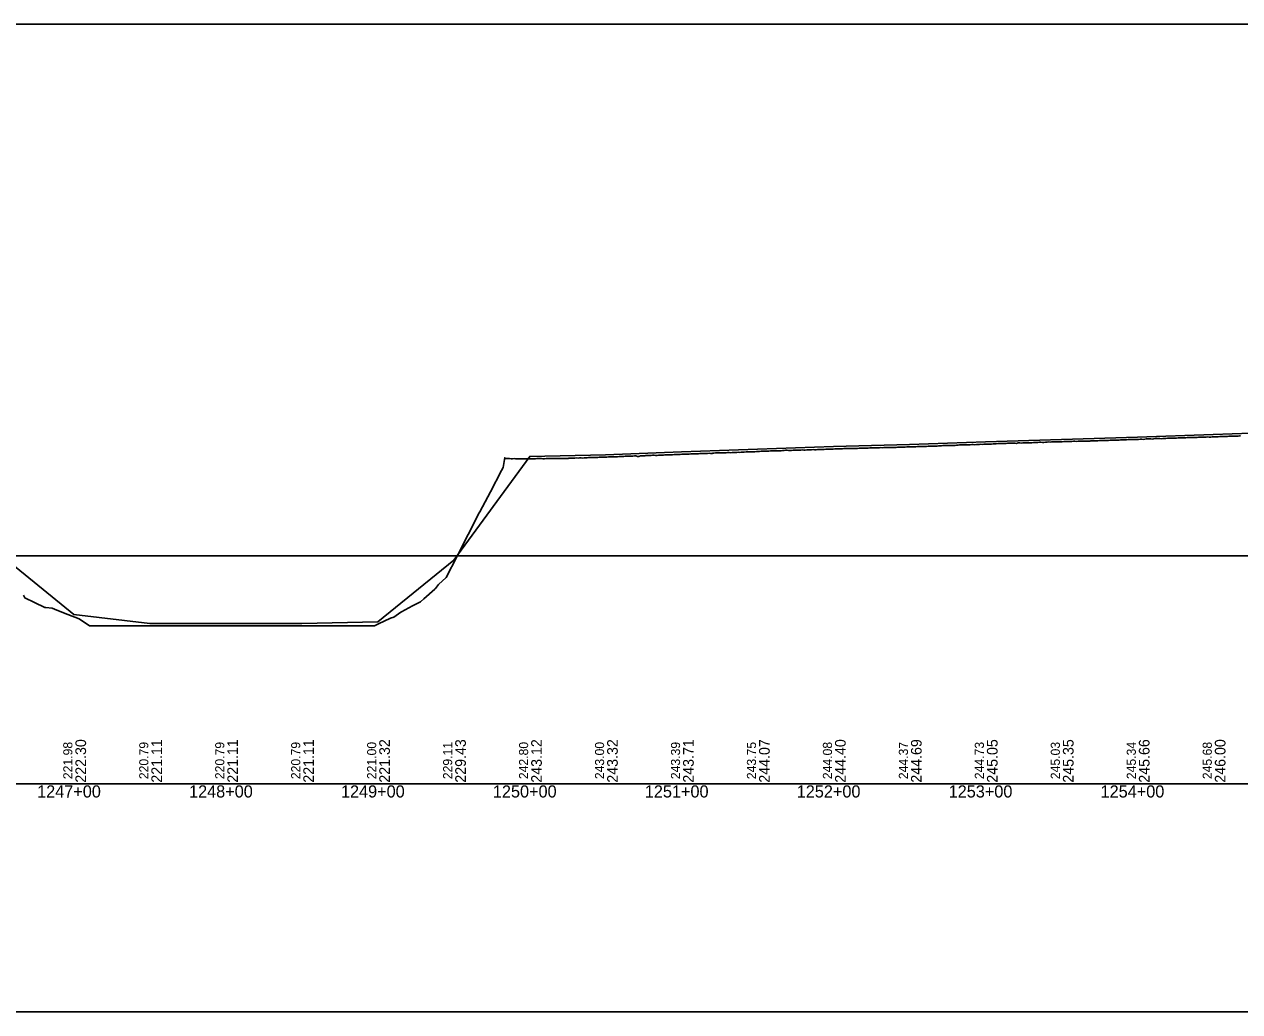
# Model space of a CAD drawing. Extents: x -3627 to 47473, y 2850 to 4350.
# Drawn here: x 12045 to 12845, y 2850 to 3500 of the extents above; entities that cross this region are included whole.
import ezdxf

# ---------------------------------------------------------------- set-up
doc = ezdxf.new("R2010")
doc.units = 0
for name, color, linetype in [('RD_DDB_Profile_EX', 7, 'Continuous'), ('RD_DDB_Profile_PR', 7, 'Continuous'), ('RD_DDB_StaTX', 7, 'Continuous'), ('RD_DDB_StripGrade', 7, 'Continuous'), ('RD_GPK_Profile_Cell', 7, 'Continuous'), ('RD_SHT_ShtClip', 7, 'Continuous')]:
    doc.layers.add(name, color=color, linetype=linetype)

msp = doc.modelspace()

# ---------------------------------------------------------------- linework, layer by layer
at = {"layer": 'RD_DDB_Profile_EX'}
for points in [[(12595.18229, 3220.917655), (12596.179708, 3220.93725), (12597.183113, 3220.978635), (12598.180536, 3220.98066), (12599.183936, 3221.051895), (12600.243634, 3221.062645), (12601.184864, 3221.115985), (12602.182411, 3221.15857), (12603.178695, 3221.15884), (12604.182196, 3221.200265), (12605.260439, 3221.213145), (12606.264547, 3221.21172), (12607.560844, 3221.29361), (12608.534436, 3221.33665), (12609.532153, 3221.269425), (12610.532749, 3221.308945), (12611.53669, 3221.37191), (12612.53861, 3221.373765), (12613.53501, 3221.41641), (12614.536917, 3221.511955), (12614.878053, 3221.49483), (12615.533435, 3221.432655), (12616.535513, 3221.43412), (12617.532093, 3221.46931), (12618.532893, 3221.442675), (12619.530743, 3221.57771), (12620.531541, 3221.586655), (12621.529385, 3221.571665), (12622.530244, 3221.572965), (12623.528267, 3221.607995), (12624.529246, 3221.69517), (12625.526012, 3221.744495), (12626.535868, 3221.80815), (12627.532631, 3221.85754), (12628.530665, 3221.856675), (12629.531642, 3221.81503), (12630.530563, 3221.942775), (12631.531715, 3221.929625), (12632.528673, 3221.97138), (12633.531093, 3222.04359), (12634.528055, 3222.042575), (12635.530473, 3222.078955), (12636.527439, 3222.12817), (12636.829683, 3222.128495), (12637.52999, 3222.12859), (12638.527152, 3222.12754), (12639.528483, 3222.220925), (12640.526929, 3222.29784), (12641.535868, 3222.24693), (12642.584716, 3222.260745), (12643.586412, 3222.31895), (12644.583336, 3222.36824), (12645.585336, 3222.368835), (12646.436473, 3222.495595), (12647.353757, 3222.53258), (12648.34842, 3222.60685), (12649.351012, 3222.628885), (12650.346788, 3222.67372), (12651.464102, 3222.666705), (12652.344042, 3222.69877), (12653.351913, 3222.771535), (12654.353461, 3222.81537), (12655.349212, 3222.817265), (12656.351829, 3222.73086), (12657.346512, 3222.826265), (12658.349128, 3222.863615), (12658.781312, 3222.86459), (12659.344062, 3222.85229), (12660.345687, 3223.07057), (12661.34833, 3223.12188), (12662.344052, 3223.11716), (12663.345693, 3223.161135), (12664.346741, 3223.158905), (12665.349383, 3223.165095), (12666.352033, 3223.239595), (12667.346775, 3223.178855), (12668.349443, 3223.278595), (12669.345137, 3223.297925), (12670.346854, 3223.24788), (12671.342538, 3223.34306), (12672.345208, 3223.35473), (12673.415731, 3223.37456), (12674.342636, 3223.520085), (12675.350711, 3223.48328), (12676.345477, 3223.50761), (12677.348174, 3223.62813), (12678.343853, 3223.60221), (12679.345637, 3223.690355), (12680.348334, 3223.68401), (12680.732941, 3223.684485), (12681.344031, 3223.68484), (12682.345844, 3223.78416), (12683.404348, 3223.78509), (12684.406534, 3223.83441), (12685.410311, 3223.939595), (12686.409477, 3223.96429), (12687.411675, 3224.007785), (12688.406596, 3223.99855), (12689.408993, 3224.047665), (12689.868477, 3224.09275), (12690.864861, 3224.093365)], [(12690.864861, 3224.093365), (12691.866756, 3224.16412), (12692.867594, 3224.223), (12693.863062, 3224.20753), (12694.864976, 3224.23389), (12695.367361, 3224.23536), (12695.865839, 3224.220465), (12696.868669, 3224.157735), (12697.864174, 3224.15199), (12698.865042, 3224.42761), (12699.867019, 3224.420735), (12700.862515, 3224.371365), (12701.863594, 3224.473825), (12702.866231, 3224.477795), (12703.861119, 3224.45435), (12704.869179, 3224.47844), (12705.864705, 3224.51287), (12706.859594, 3224.46813), (12707.868499, 3224.584375), (12708.863388, 3224.68962), (12710.00178, 3224.7055), (12710.867014, 3224.69833), (12711.861945, 3224.74788), (12712.870894, 3224.8242), (12713.865824, 3224.873825), (12714.86139, 3224.755295), (12715.868864, 3224.73955), (12716.864429, 3224.918405), (12717.31899, 3224.96256), (12717.867154, 3225.026845), (12718.868374, 3225.06753), (12719.863989, 3225.022375), (12720.866088, 3225.04147), (12721.867104, 3225.03765), (12722.862724, 3225.03188), (12723.865686, 3225.073805), (12724.866703, 3225.186305), (12725.894757, 3225.1893), (12726.890599, 3225.210795), (12727.891368, 3225.117825), (12728.894669, 3225.27641), (12729.890522, 3225.27569), (12730.261901, 3225.27701), (12731.364928, 3225.34085), (12731.953409, 3225.40041), (12732.365101, 3225.425735), (12733.365446, 3225.421435), (12734.259436, 3225.33305), (12735.357693, 3225.475515), (12736.25508, 3225.52136), (12737.361785, 3225.41973), (12738.262719, 3225.510875), (12739.353989, 3225.54352), (12740.354619, 3225.544205), (12741.355249, 3225.56623), (12742.260835, 3225.612275), (12743.347549, 3225.683875), (12744.348175, 3225.680045), (12745.257042, 3225.680785), (12746.264132, 3225.684135), (12746.587829, 3225.71773), (12747.345551, 3225.782475), (12748.346474, 3225.87858), (12749.347028, 3225.85043), (12750.261589, 3225.850775), (12751.340221, 3225.890415), (12752.341142, 3225.94504), (12753.342063, 3226.024545), (12753.905039, 3226.02482), (12754.259571, 3226.024835), (12755.338437, 3225.95421), (12756.339661, 3225.99626), (12757.340885, 3226.042305), (12758.342109, 3226.070255), (12759.334614, 3226.214125), (12760.335506, 3226.260055), (12761.258446, 3226.21398), (12762.329549, 3226.26164), (12763.253864, 3226.307485), (12764.336523, 3226.328375), (12765.262283, 3226.32813), (12766.33049, 3226.418115), (12767.33202, 3226.414065), (12768.539458, 3226.460045), (12769.175199, 3226.45608), (12770.168504, 3226.507445), (12771.17459, 3226.57013), (12772.167529, 3226.624755), (12773.168578, 3226.64181), (12774.170276, 3226.662735), (12775.167957, 3226.713035), (12776.169731, 3226.71568), (12777.163226, 3226.68401), (12778.165172, 3226.76907), (12779.17151, 3226.91346), (12780.164991, 3226.91447), (12781.166942, 3226.723725), (12782.173279, 3226.842035), (12783.173878, 3227.032835), (12784.167997, 3227.081365), (12785.161714, 3227.131865)], [(12785.161714, 3227.131865), (12786.1683, 3227.13607), (12787.170487, 3226.94517), (12788.164201, 3227.17857), (12789.166399, 3227.237655), (12790.164483, 3227.243325), (12790.491087, 3227.25927), (12791.166854, 3227.28867), (12792.169305, 3227.240745), (12793.16327, 3227.158285), (12794.169761, 3227.348135), (12795.172211, 3227.393415), (12796.165543, 3227.39367), (12797.172358, 3227.4871), (12798.166415, 3227.48717), (12799.169122, 3227.489035), (12800.171829, 3227.583735), (12801.170409, 3227.58551), (12802.173124, 3227.583785), (12803.167376, 3227.587345), (12804.170109, 3227.72815), (12805.176804, 3227.735715), (12806.171327, 3227.78912), (12807.159993, 3227.77991), (12808.162271, 3227.73218), (12809.161123, 3227.829945), (12810.163394, 3227.92425), (12810.607658, 3227.923805), (12811.607457, 3227.97565), (12812.607261, 3227.977445), (12813.608652, 3227.97141), (12814.608492, 3227.93842), (12815.608331, 3228.035945), (12816.601985, 3228.085405), (12817.609091, 3228.131475), (12818.608943, 3228.179205), (12819.759926, 3228.18809), (12820.603512, 3228.23359), (12821.610676, 3228.28317), (12822.610557, 3228.284335), (12823.604704, 3228.32994), (12824.604578, 3228.28841), (12825.61175, 3228.288015), (12826.605897, 3228.38735), (12827.077136, 3228.387865), (12827.605794, 3228.39193), (12828.60571, 3228.431955), (12829.607192, 3228.47554), (12830.60711, 3228.537525), (12831.607029, 3228.584715), (12832.601218, 3228.630055), (12833.608424, 3228.675595), (12834.608353, 3228.726485), (12835.60259, 3228.68633), (12836.609825, 3228.685405), (12837.609788, 3228.782185), (12838.604033, 3228.834775), (12839.603521, 3228.87755), (12840.610737, 3228.876525), (12841.711556, 3228.926985), (12842.604985, 3228.929475), (12843.60499, 3228.97197), (12844.61223, 3229.07455), (12845.226336, 3229.07937)], [(12403.155446, 3214.32161), (12404.155624, 3214.37354), (12405.155593, 3214.378645), (12406.14949, 3214.327475), (12407.157063, 3214.42356), (12408.150754, 3214.51931), (12409.150929, 3214.474285), (12410.158497, 3214.575015), (12411.152122, 3214.62359), (12412.152229, 3214.47825), (12413.152336, 3214.623885), (12414.153373, 3214.66987), (12415.153479, 3214.674395), (12416.147288, 3214.721535), (12417.31339, 3214.770155), (12418.149762, 3214.77205), (12419.143576, 3214.770485), (12420.143581, 3214.769125), (12421.151098, 3214.770695), (12422.144906, 3214.867765), (12423.144911, 3214.963795), (12424.138711, 3214.963615), (12424.6306, 3215.01186), (12425.146214, 3215.062375), (12426.146169, 3215.11345), (12427.139913, 3214.964155), (12428.139867, 3215.1078), (12429.147356, 3215.2041), (12430.238755, 3215.255995), (12431.238718, 3215.20813), (12432.238669, 3215.259025), (12433.238591, 3215.3563), (12434.232174, 3215.35327), (12435.239699, 3215.304965), (12436.239623, 3215.40347), (12437.239547, 3215.404115), (12438.233299, 3215.55106), (12439.265019, 3215.554825), (12440.233108, 3215.648015), (12441.232992, 3215.647405), (12442.240499, 3215.6947), (12443.2342, 3215.74443), (12444.234197, 3215.743835), (12445.23408, 3215.74321), (12446.233963, 3215.840845), (12446.582229, 3215.840105), (12447.227618, 3215.84027), (12448.235104, 3215.4945), (12449.23495, 3215.541995), (12450.234796, 3215.885825), (12451.234642, 3215.935735), (12452.228267, 3216.034015), (12453.22811, 3216.03382), (12453.899439, 3216.099035), (12454.23561, 3216.12916), (12455.23542, 3216.128745), (12456.23523, 3216.12829), (12457.2288, 3216.225145), (12458.230101, 3216.273635), (12459.229844, 3216.27262), (12460.237269, 3216.220475), (12461.230597, 3216.21758), (12462.230338, 3216.416035), (12463.392934, 3216.415375), (12464.392755, 3216.464185), (12465.3848, 3216.464125), (12466.384575, 3216.51236), (12467.384383, 3216.511475), (12468.533858, 3216.56784), (12469.383891, 3216.60896), (12470.38988, 3216.65864), (12471.389649, 3216.65767), (12472.389387, 3216.70616), (12473.381381, 3216.7559), (12474.381134, 3216.75476), (12475.380858, 3216.85328), (12475.851068, 3216.87669), (12476.386886, 3216.903185), (12477.386587, 3216.951605), (12478.44822, 3216.953095), (12479.387634, 3216.997585), (12480.389075, 3216.993955), (12481.381579, 3216.99333), (12482.387694, 3217.04466), (12483.389107, 3217.1432), (12484.390722, 3217.14151), (12485.388279, 3217.140175), (12486.389076, 3217.185465), (12487.389808, 3217.18416), (12488.395988, 3217.3305), (12489.388433, 3217.429535), (12490.485487, 3217.429245), (12491.390193, 3217.42688), (12492.390828, 3217.42425), (12493.391898, 3217.466335), (12494.39787, 3217.556505), (12495.398618, 3217.598785), (12496.399708, 3217.51805), (12497.392121, 3217.51257), (12497.802697, 3217.59346), (12498.610126, 3217.743655)], [(12498.610126, 3217.743655), (12499.610562, 3217.794505), (12500.610605, 3217.83271), (12501.603491, 3217.880565), (12502.60881, 3217.879035), (12503.608834, 3217.927865), (12504.609354, 3217.98646), (12505.119907, 3217.98586), (12505.614945, 3217.985235), (12506.608, 3217.986555), (12507.607639, 3218.075925), (12508.607661, 3218.033295), (12509.613778, 3217.974385), (12510.613781, 3218.058975), (12511.60704, 3218.22697), (12512.612023, 3218.129675), (12513.612024, 3218.191815), (12514.612737, 3218.23688), (12515.605441, 3218.171275), (12516.610835, 3218.265175), (12517.611024, 3218.40162), (12518.611, 3218.4326), (12519.754326, 3218.513135), (12520.60993, 3218.559705), (12521.609927, 3218.550825), (12522.610147, 3218.5854), (12523.615375, 3218.639335), (12524.643776, 3218.6475), (12525.637873, 3218.65189), (12526.642429, 3218.73815), (12527.071536, 3218.757905), (12527.64398, 3218.784805), (12528.645591, 3218.82479), (12529.639177, 3218.91564), (12530.644359, 3218.957265), (12531.645214, 3218.90305), (12532.756403, 3218.999685), (12533.760336, 3219.015525), (12534.758563, 3219.05773), (12535.75647, 3219.11451), (12536.75965, 3219.165445), (12537.758722, 3219.20777), (12538.7578, 3219.25004), (12539.759811, 3219.3084), (12540.758881, 3219.26492), (12541.757141, 3219.271205), (12542.761192, 3219.314985), (12543.760325, 3219.36414), (12544.757462, 3219.463235), (12545.761516, 3219.59987), (12546.759825, 3219.591405), (12547.758968, 3219.512195), (12549.023166, 3219.519765), (12549.760182, 3219.50475), (12550.759386, 3219.588935), (12551.762656, 3219.646635), (12552.761864, 3219.65277), (12553.759016, 3219.61638), (12554.763129, 3219.70221), (12555.762344, 3219.73615), (12556.760735, 3219.776855), (12557.764902, 3219.734795), (12558.762081, 3219.72105), (12559.761373, 3219.804505), (12560.765541, 3219.87014), (12561.76396, 3219.887725), (12562.761998, 3219.970915), (12563.854831, 3220.036745), (12564.853753, 3219.93521), (12565.854111, 3219.975475), (12566.856845, 3220.09168), (12567.696497, 3220.17396), (12568.191237, 3220.125315), (12569.186966, 3220.092935), (12570.189849, 3220.101105), (12571.18693, 3220.144685), (12572.189935, 3220.221435), (12573.18709, 3220.272805), (12574.182927, 3220.297365), (12575.187249, 3220.297145), (12576.183086, 3220.341025), (12577.187409, 3220.37563), (12578.292005, 3220.44229), (12579.18639, 3220.464635), (12580.183614, 3220.457975), (12581.186775, 3220.457725), (12582.183993, 3220.501145), (12583.187161, 3220.593425), (12584.184373, 3220.644375), (12585.18032, 3220.680885), (12585.609214, 3220.680635), (12586.183565, 3220.68776), (12587.180875, 3220.73844), (12588.184168, 3220.737825), (12589.181477, 3220.788505), (12590.184771, 3220.83052), (12591.18208, 3220.803245), (12592.185374, 3220.802685), (12593.182711, 3220.84589), (12594.178881, 3220.87456), (12595.18229, 3220.917655)], [(12073.404531, 3111.454815), (12080.792382, 3108.519355), (12087.569175, 3103.95), (12088.038951, 3103.95), (12088.911974, 3103.95), (12093.575737, 3103.95), (12094.488472, 3103.95), (12095.356161, 3103.95), (12102.67337, 3103.95), (12107.565722, 3103.95), (12109.99058, 3103.95), (12117.30779, 3103.95), (12124.625, 3103.95), (12131.942209, 3103.95), (12139.259419, 3103.95), (12146.576629, 3103.95), (12153.893839, 3103.95), (12161.211048, 3103.95), (12168.528258, 3103.95), (12175.845468, 3103.95), (12183.162678, 3103.95), (12190.479887, 3103.95), (12197.797097, 3103.95), (12205.114307, 3103.95), (12212.431517, 3103.95), (12219.748726, 3103.95), (12227.065936, 3103.95), (12234.383146, 3103.95), (12235.095961, 3103.95), (12241.700356, 3103.95), (12249.017566, 3103.95), (12256.334775, 3103.95), (12263.651985, 3103.95), (12270.969195, 3103.95), (12275.22801, 3103.95), (12278.286405, 3105.501115), (12281.555999, 3107.16006), (12285.711233, 3109.05109), (12287.94298, 3109.62094), (12292.581701, 3113.088695), (12292.920824, 3113.267345), (12300.238034, 3117.123625), (12305.482142, 3119.888535), (12307.555244, 3121.735095), (12314.872453, 3128.25292), (12315.357578, 3128.685065), (12317.396575, 3131.313705), (12322.392704, 3135.903065), (12329.506873, 3149.814835), (12336.824083, 3164.12391), (12344.141292, 3178.43322), (12344.483747, 3179.102925), (12351.49971, 3192.330345), (12358.775712, 3206.312755), (12359.818314, 3208.3163), (12360.925095, 3214.820055), (12361.044836, 3214.11483), (12362.092902, 3214.072145), (12363.051072, 3214.072265), (12364.095029, 3214.0708), (12365.052967, 3214.02273), (12366.092922, 3214.016505), (12367.091436, 3214.065685), (12368.085717, 3213.969245), (12369.056986, 3213.921345), (12370.0511, 3213.971205), (12371.089265, 3213.96835), (12372.05322, 3213.96952), (12373.091223, 3214.004035), (12373.410131, 3213.988405), (12374.05513, 3213.956705), (12375.093042, 3213.918255), (12376.087238, 3213.918), (12377.051385, 3213.967185), (12378.089031, 3214.01597), (12379.053305, 3214.016945), (12380.055428, 3214.0176), (12381.084722, 3214.018995), (12382.092476, 3214.067115), (12383.086358, 3214.11489), (12384.086787, 3214.11211), (12385.088225, 3214.06263), (12386.082105, 3214.012185), (12387.089866, 3213.963805), (12388.083968, 3214.063385), (12389.057462, 3214.111455), (12390.085453, 3214.212495), (12391.092919, 3214.212185), (12392.156326, 3214.21107), (12393.156648, 3214.215005), (12394.156751, 3214.072325), (12395.361761, 3214.071605), (12396.15844, 3214.074505), (12397.158473, 3214.126655), (12398.152446, 3214.175745), (12399.160078, 3214.27357), (12400.153836, 3214.269405), (12401.154084, 3214.221535), (12402.154332, 3214.22369), (12402.67897, 3214.27507), (12403.155446, 3214.32161)], [(12044.135692, 3124.158525), (12045.05235, 3122.38407), (12051.452902, 3119.29524), (12058.188175, 3116.04544), (12058.770112, 3115.98718), (12063.079715, 3115.55677), (12066.087322, 3114.361955), (12073.404531, 3111.454815)]]:
    msp.add_lwpolyline(points, dxfattribs=at)
at = {"layer": 'RD_DDB_Profile_PR'}
msp.add_lwpolyline([(12027.33, 3152.016), (12077.33, 3111.495), (12127.33, 3105.55), (12177.33, 3105.55), (12227.33, 3105.55), (12277.33, 3106.616), (12327.33, 3147.158), (12377.33, 3215.5805), (12427.33, 3216.5915), (12477.33, 3218.549), (12527.33, 3220.37), (12577.33, 3221.984), (12627.33, 3223.4475), (12677.33, 3225.226), (12727.33, 3226.77), (12777.33, 3228.298), (12827.33, 3229.99), (12877.33, 3231.692)], dxfattribs=at)
at = {"layer": 'RD_GPK_Profile_Cell'}
msp.add_line((1000, 3000), (46705.077602, 3000), dxfattribs=at)
at = {"layer": 'RD_SHT_ShtClip'}
for points in [[(13000.165, 3000), (13000.165, 3500), (13000.165, 3500), (11500.33, 3500), (11500.33, 3000)], [(11480.33, 3150), (13020, 3150), (13020, 2850), (11480.33, 2850)]]:
    msp.add_lwpolyline(points, close=True, dxfattribs=at)

# ---------------------------------------------------------------- texts
at = {"layer": 'RD_DDB_StaTX'}
for s, p in [('1247+00', (12053.125471, 2991)), ('1248+00', (12153.125471, 2991)), ('1249+00', (12253.125471, 2991)), ('1250+00', (12353.125471, 2991)), ('1251+00', (12453.125471, 2991)), ('1252+00', (12553.125471, 2991)), ('1253+00', (12653.125471, 2991)), ('1254+00', (12753.125471, 2991))]:
    msp.add_text(s, height=8, dxfattribs=at).set_placement(p)
at = {"layer": 'RD_DDB_StripGrade'}
for s, height, p in [('221.98', 6, (12076.33, 3003.073688)), ('222.30', 7, (12085.33, 3000.75)), ('220.79', 6, (12126.33, 3003.073688)), ('221.11', 7, (12135.33, 3000.75)), ('220.79', 6, (12176.33, 3003.073688)), ('221.11', 7, (12185.33, 3000.75)), ('220.79', 6, (12226.33, 3003.073688)), ('221.11', 7, (12235.33, 3000.75)), ('221.00', 6, (12276.33, 3003.073688)), ('221.32', 7, (12285.33, 3000.75)), ('229.11', 6, (12326.33, 3003.073688)), ('229.43', 7, (12335.33, 3000.75)), ('242.80', 6, (12376.33, 3003.073688)), ('243.12', 7, (12385.33, 3000.75)), ('243.00', 6, (12426.33, 3003.073688)), ('243.32', 7, (12435.33, 3000.75)), ('243.39', 6, (12476.33, 3003.073688)), ('243.71', 7, (12485.33, 3000.75)), ('243.75', 6, (12526.33, 3003.073688)), ('244.07', 7, (12535.33, 3000.75)), ('244.08', 6, (12576.33, 3003.073688)), ('244.40', 7, (12585.33, 3000.75)), ('244.37', 6, (12626.33, 3003.073688)), ('244.69', 7, (12635.33, 3000.75)), ('244.73', 6, (12676.33, 3003.073688)), ('245.05', 7, (12685.33, 3000.75)), ('245.03', 6, (12726.33, 3003.073688)), ('245.35', 7, (12735.33, 3000.75)), ('245.34', 6, (12776.33, 3003.073688)), ('245.66', 7, (12785.33, 3000.75)), ('245.68', 6, (12826.33, 3003.073688)), ('246.00', 7, (12835.33, 3000.75))]:
    msp.add_text(s, height=height, rotation=90, dxfattribs=at).set_placement(p)

doc.saveas('drawing.dxf')
